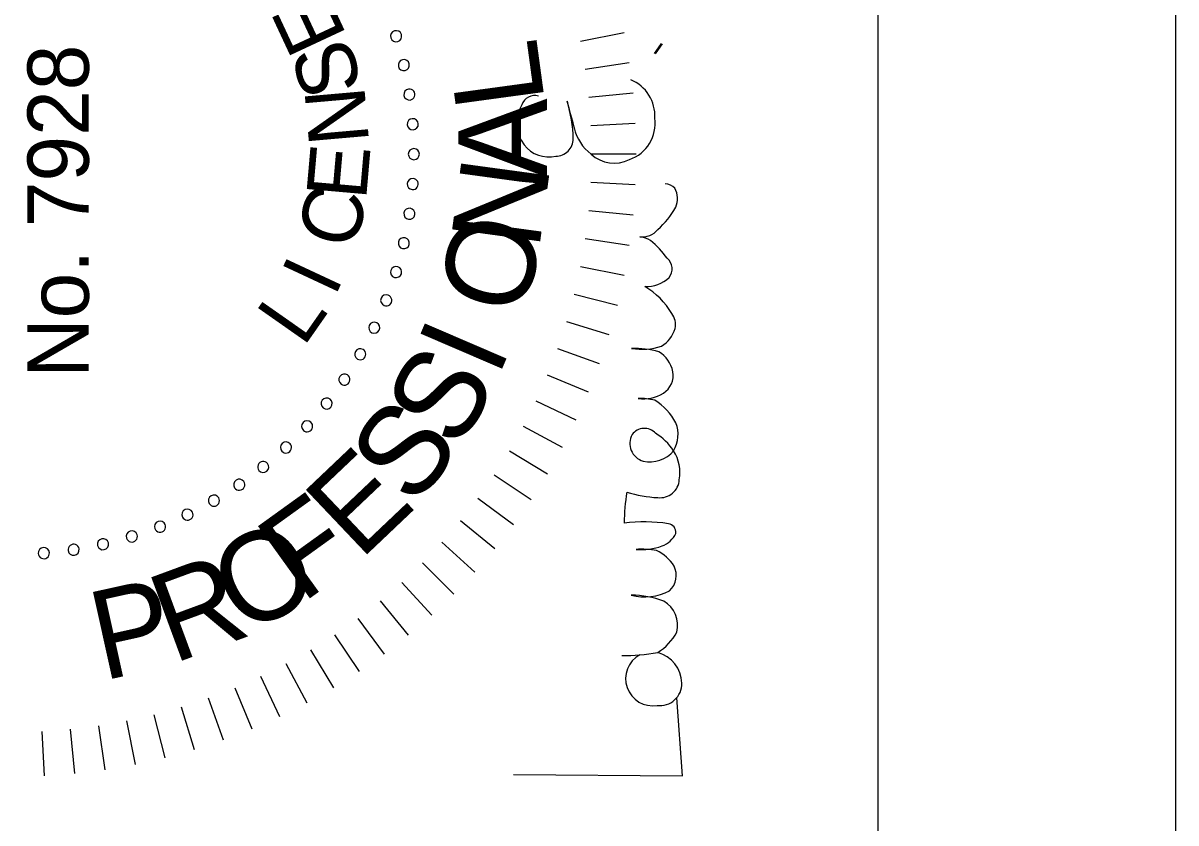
# Model space of a CAD drawing. Extents: x 916887 to 917745, y 329243 to 329793.
# Drawn here: x 917700.26 to 917737.16, y 329615.23 to 329640.82 of the extents above; entities that cross this region are included whole.
import ezdxf

# ---------------------------------------------------------------- set-up
doc = ezdxf.new("R2010")
doc.units = 0
for name, color, linetype in [('Border', 7, 'Continuous'), ('Default', 7, 'Continuous'), ('PLOT BOUNDARY', 7, 'Continuous')]:
    doc.layers.add(name, color=color, linetype=linetype)

# ---------------------------------------------------------------- blocks, each defined once
blk = doc.blocks.new('STAMP')
at = {"layer": 'Default'}
for p, q in [((-0.007955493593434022, 0.0011091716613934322), (-0.007387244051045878, 0.0011370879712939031)), ((-0.007926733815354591, 0.0007192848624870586), (-0.007360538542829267, 0.0007750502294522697)), ((-0.007878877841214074, 0.0003312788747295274), (-0.0073161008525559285, 0.00041475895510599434)), ((-0.007812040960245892, -5.391156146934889e-05), (-0.007254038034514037, 5.708212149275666e-05)), ((-0.0077263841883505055, -0.0004353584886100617), (-0.0071744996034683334, -0.00029711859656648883)), ((-0.007622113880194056, -0.0008121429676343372), (-0.007077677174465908, -0.0006469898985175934)), ((-0.00749948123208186, -0.0011833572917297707), (-0.0069638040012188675, -0.00099168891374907)), ((-0.007358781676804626, -0.0015481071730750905), (-0.006833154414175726, -0.001330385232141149)), ((-0.007200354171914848, -0.0019055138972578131), (-0.006686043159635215, -0.0016622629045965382)), ((-0.007024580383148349, -0.0022547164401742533), (-0.0065228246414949, -0.001986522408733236)), ((-0.006831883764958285, -0.002594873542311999), (-0.006343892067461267, -0.0023023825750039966)), ((-0.006622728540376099, -0.002925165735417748), (-0.0061496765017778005, -0.0026090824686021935)), ((-0.00639761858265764, -0.0032447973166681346), (-0.005940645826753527, -0.0029058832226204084)), ((-0.006157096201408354, -0.003552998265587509), (-0.005717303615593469, -0.0031920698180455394)), ((-0.005901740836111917, -0.003849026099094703), (-0.005480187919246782, -0.0034669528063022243)), ((-0.0056321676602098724, -0.0041321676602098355), (-0.00522986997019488, -0.003729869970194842)), ((-0.005349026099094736, -0.004401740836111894), (-0.004966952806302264, -0.003980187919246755)), ((-0.0050529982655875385, -0.004657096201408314), (-0.004692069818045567, -0.004217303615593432)), ((-0.004744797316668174, -0.0048976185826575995), (-0.004405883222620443, -0.004440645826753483)), ((-0.0044251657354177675, -0.005122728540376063), (-0.004109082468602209, -0.004649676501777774)), ((-0.004094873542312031, -0.005331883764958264), (-0.0038023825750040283, -0.004843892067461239)), ((-0.0037547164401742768, -0.005524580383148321), (-0.0034865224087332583, -0.005022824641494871)), ((-0.003405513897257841, -0.005700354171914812), (-0.0031622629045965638, -0.0051860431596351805)), ((-0.003048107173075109, -0.005858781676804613), (-0.0028303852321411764, -0.005333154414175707)), ((-0.0026833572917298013, -0.005999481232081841), (-0.002491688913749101, -0.005463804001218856)), ((-0.0023121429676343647, -0.006122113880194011), (-0.0021469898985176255, -0.005577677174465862)), ((-0.0019353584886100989, -0.006226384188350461), (-0.0017971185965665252, -0.005674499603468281)), ((-0.0015539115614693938, -0.006312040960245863), (-0.0014429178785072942, -0.005754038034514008)), ((0.0015539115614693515, -0.006312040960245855), (0.0014429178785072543, -0.005754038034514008)), ((-0.001168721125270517, -0.006378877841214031), (-0.0010852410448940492, -0.005816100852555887)), ((-0.0007807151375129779, -0.006426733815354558), (-0.0007249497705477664, -0.0058605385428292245)), ((-0.00039082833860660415, -0.006455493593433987), (-0.00036291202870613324, -0.005887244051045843)), ((-2.0539125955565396e-17, -0.006465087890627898), (-2.0539125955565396e-17, -0.005896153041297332)), ((0.0003908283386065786, -0.0064554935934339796), (0.0003629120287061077, -0.005887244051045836)), ((0.0007807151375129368, -0.006426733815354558), (0.0007249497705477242, -0.005860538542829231)), ((0.0011687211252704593, -0.006378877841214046), (0.0010852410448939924, -0.005816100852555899)), ((0.001282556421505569, -0.006716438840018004), (0.001411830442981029, -0.006805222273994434)), ((0.0012888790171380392, -0.0067038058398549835), (0.0014181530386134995, -0.006792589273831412))]:
    blk.add_line(p, q, dxfattribs=at)
blk.add_lwpolyline([(-0.007938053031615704, -0.004895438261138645), (-0.007956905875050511, -0.007061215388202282), (-0.0069577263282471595, -0.006985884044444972)], dxfattribs=at)
for centre, radius, start, end in [((-0.005106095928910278, 0.0011173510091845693), 7.111685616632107e-05, 94.28571428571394, 274.28571428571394), ((-0.005106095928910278, 0.0011173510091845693), 7.11168561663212e-05, 274.28571428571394, 94.28571428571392), ((-0.005063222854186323, 0.0007368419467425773), 7.111685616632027e-05, 98.5714285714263, 278.5714285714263), ((-0.005063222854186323, 0.0007368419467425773), 7.111685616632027e-05, 278.5714285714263, 98.5714285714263), ((-0.0049920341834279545, 0.00036060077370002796), 7.11168561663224e-05, 102.8571428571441, 282.8571428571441), ((-0.0049920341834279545, 0.00036060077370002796), 7.11168561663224e-05, 282.8571428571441, 102.85714285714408), ((-0.004892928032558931, -9.26841668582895e-06), 7.111685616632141e-05, 107.14285714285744, 287.14285714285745), ((-0.004892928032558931, -9.26841668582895e-06), 7.111685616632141e-05, 287.14285714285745, 107.14285714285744), ((-0.004766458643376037, -0.00037069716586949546), 7.111685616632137e-05, 111.42857142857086, 291.4285714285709), ((-0.004766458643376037, -0.00037069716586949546), 7.111685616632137e-05, 291.4285714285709, 111.42857142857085), ((-0.0046133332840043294, -0.0007216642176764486), 7.1116856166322e-05, 115.71428571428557, 295.71428571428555), ((-0.0046133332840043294, -0.0007216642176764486), 7.1116856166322e-05, 295.71428571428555, 115.71428571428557), ((-0.004434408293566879, -0.0010602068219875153), 7.111685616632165e-05, 119.99999999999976, 299.9999999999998), ((-0.004434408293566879, -0.0010602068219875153), 7.111685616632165e-05, 299.9999999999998, 119.99999999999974), ((-0.004230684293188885, -0.0013844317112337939), 7.111685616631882e-05, 124.28571428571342, 304.2857142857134), ((-0.004230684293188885, -0.0013844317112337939), 7.111685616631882e-05, 304.2857142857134, 124.28571428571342), ((-0.004003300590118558, -0.0016925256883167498), 7.111685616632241e-05, 308.5714285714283, 128.57142857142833), ((-0.004003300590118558, -0.0016925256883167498), 7.111685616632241e-05, 128.57142857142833, 308.5714285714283), ((-0.003753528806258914, -0.0019827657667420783), 7.11168561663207e-05, 312.85714285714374, 132.85714285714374), ((-0.003753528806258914, -0.0019827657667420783), 7.11168561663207e-05, 132.85714285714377, 312.8571428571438), ((-0.0034827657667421, -0.002253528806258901), 7.111685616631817e-05, 137.14285714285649, 317.1428571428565), ((-0.0034827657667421, -0.002253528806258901), 7.111685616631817e-05, 317.1428571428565, 137.14285714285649), ((-0.0031925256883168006, -0.0025033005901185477), 7.111685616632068e-05, 141.42857142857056, 321.42857142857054), ((-0.0031925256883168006, -0.0025033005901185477), 7.111685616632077e-05, 321.42857142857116, 141.4285714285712), ((-0.0028844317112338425, -0.0027306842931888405), 7.111685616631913e-05, 145.7142857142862, 325.71428571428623), ((-0.0028844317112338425, -0.0027306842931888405), 7.111685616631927e-05, 325.7142857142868, 145.71428571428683), ((-0.0025602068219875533, -0.0029344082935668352), 7.111685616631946e-05, 149.99999999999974, 329.9999999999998), ((-0.0025602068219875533, -0.0029344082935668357), 7.111685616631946e-05, 329.9999999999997, 149.99999999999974), ((-0.0022216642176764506, -0.0031133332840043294), 7.111685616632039e-05, 154.2857142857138, 334.28571428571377), ((-0.0022216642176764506, -0.0031133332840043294), 7.111685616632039e-05, 334.2857142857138, 154.2857142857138), ((-0.0018706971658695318, -0.003266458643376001), 7.111685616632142e-05, 158.57142857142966, 338.5714285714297), ((-0.0018706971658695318, -0.0032664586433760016), 7.111685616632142e-05, 338.57142857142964, 158.57142857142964), ((-0.0015092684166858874, -0.003392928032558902), 7.111685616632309e-05, 162.85714285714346, 342.85714285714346), ((-0.0015092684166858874, -0.003392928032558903), 7.111685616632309e-05, 342.85714285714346, 162.85714285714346), ((0.0015092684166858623, -0.0033929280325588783), 7.111685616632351e-05, 17.142857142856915, 197.1428571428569), ((0.0015092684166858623, -0.0033929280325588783), 7.111685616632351e-05, 197.1428571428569, 17.14285714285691), ((-0.0011393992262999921, -0.0034920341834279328), 7.111685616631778e-05, 167.14285714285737, 347.14285714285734), ((-0.0011393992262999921, -0.0034920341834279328), 7.111685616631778e-05, 347.14285714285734, 167.14285714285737), ((-0.0007631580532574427, -0.003563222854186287), 7.111685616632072e-05, 351.4285714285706, 171.4285714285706), ((-0.0003826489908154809, -0.003606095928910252), 7.111685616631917e-05, 355.7142857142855, 175.7142857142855), ((0.0003826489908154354, -0.0036060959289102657), 7.111685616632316e-05, 4.285714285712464, 184.28571428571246), ((0.0007631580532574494, -0.0035632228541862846), 7.111685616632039e-05, 8.571428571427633, 188.57142857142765), ((0.0011393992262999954, -0.0034920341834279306), 7.111685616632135e-05, 12.857142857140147, 192.85714285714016), ((0.0011393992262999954, -0.0034920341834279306), 7.111685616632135e-05, 192.85714285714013, 12.857142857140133), ((-0.0007631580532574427, -0.003563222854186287), 7.111685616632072e-05, 171.4285714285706, 351.4285714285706), ((-0.0003826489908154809, -0.003606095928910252), 7.111685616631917e-05, 175.71428571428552, 355.71428571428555), ((-1.2628786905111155e-17, -0.0036204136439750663), 7.111685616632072e-05, 0, 180), ((-1.2628786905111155e-17, -0.0036204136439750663), 7.111685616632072e-05, 180, 0), ((0.0003826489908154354, -0.0036060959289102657), 7.111685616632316e-05, 184.28571428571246, 4.285714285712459), ((0.0007631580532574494, -0.0035632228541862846), 7.111685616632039e-05, 188.57142857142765, 8.571428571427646), ((0.00039604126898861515, -0.005375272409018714), 0.00043958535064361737, 57.64755033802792, 128.97245422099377), ((0.0005805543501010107, -0.005165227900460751), 0.00016909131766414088, 342.3611945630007, 72.54487353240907), ((0.00036114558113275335, -0.0053488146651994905), 0.0003972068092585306, 127.45926190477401, 192.9614203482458), ((0.00019608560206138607, -0.005439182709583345), 0.0002220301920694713, 179.67057284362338, 269.694601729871), ((0.00015503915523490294, -0.003868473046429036), 0.001793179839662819, 271.2738092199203, 287.01217780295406), ((0.002166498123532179, -0.011827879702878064), 0.006419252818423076, 103.3923944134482, 106.55297850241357), ((0.0004564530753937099, -0.0062299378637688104), 0.0005678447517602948, 102.0773813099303, 143.39383108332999), ((0.00031613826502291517, -0.006186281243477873), 0.0004319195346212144, 136.9297266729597, 206.7934360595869), ((-0.00671307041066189, -0.006678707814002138), 0.0003465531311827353, 28.430349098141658, 189.68707560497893), ((-0.003955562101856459, -0.006312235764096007), 0.002461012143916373, 179.30402472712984, 190.0665804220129), ((-0.007015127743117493, -0.0065631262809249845), 0.0023079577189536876, 352.1195763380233, 6.249520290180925), ((-0.004786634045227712, -0.009314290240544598), 0.003003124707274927, 81.15725195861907, 88.74550427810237), ((-0.002857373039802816, -0.006810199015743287), 0.001539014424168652, 162.47862001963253, 177.5735090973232), ((-0.007040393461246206, -0.006369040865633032), 0.0013973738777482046, 341.03759348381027, 358.5906169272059), ((-0.004987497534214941, -0.006577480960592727), 0.0006786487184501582, 165.1377733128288, 207.96825790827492), ((-0.006329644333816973, -0.006519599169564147), 0.0012732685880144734, 350.5388137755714, 2.446920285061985), ((-0.004310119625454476, -0.006538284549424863), 0.0007509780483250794, 174.41813129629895, 200.30191948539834), ((-0.0037000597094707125, -0.006623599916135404), 0.00023723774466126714, 61.91684207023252, 163.66717131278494), ((-0.0037052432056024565, -0.0065716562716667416), 0.0001960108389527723, 312.7382758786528, 53.40100716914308), ((-0.003974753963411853, -0.006503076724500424), 0.0008496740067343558, 346.26214121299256, 0.7257075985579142), ((-0.002682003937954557, -0.006568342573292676), 0.00044961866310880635, 170.2648919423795, 213.2954708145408), ((-0.00388024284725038, -0.006412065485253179), 0.0013948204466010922, 345.72048696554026, 0.12433676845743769), ((-0.0016914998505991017, -0.006545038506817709), 0.0008054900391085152, 170.27954956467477, 197.78532003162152), ((0.0003962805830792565, -0.006217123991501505), 0.0004936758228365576, 199.38474076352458, 277.55079490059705), ((0.0004891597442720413, -0.006207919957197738), 0.0004993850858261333, 266.784921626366, 337.7362429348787), ((-0.0035430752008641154, -0.006644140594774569), 0.0003944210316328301, 167.2189950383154, 230.16055614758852), ((-0.002536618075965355, -0.006083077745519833), 0.0009765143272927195, 300.6803608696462, 329.51258202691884), ((-0.0012666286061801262, -0.006594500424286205), 0.00042878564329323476, 177.86300386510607, 223.17874837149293), ((-0.0013865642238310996, -0.006474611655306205), 0.0003320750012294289, 327.8843366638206, 353.1980671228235), ((-0.0008025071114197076, -0.006544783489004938), 0.0002561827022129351, 173.08541670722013, 230.55848375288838), ((-0.006777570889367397, -0.006772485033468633), 0.00027937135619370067, 172.70712454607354, 271.16395527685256), ((-0.006783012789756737, -0.006633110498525), 0.0004188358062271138, 271.5209447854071, 344.87406906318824), ((-0.005754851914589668, -0.006345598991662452), 0.0007393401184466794, 212.4592088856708, 240.63114206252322), ((-0.0055308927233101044, -0.006522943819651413), 0.0005014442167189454, 301.1133493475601, 335.74975916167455), ((-0.004152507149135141, -0.006775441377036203), 0.00024439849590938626, 172.85451562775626, 266.8151593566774), ((-0.00421927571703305, -0.006314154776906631), 0.0007614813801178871, 303.79189499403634, 328.18256979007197), ((-0.0038004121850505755, -0.006299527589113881), 0.000766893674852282, 298.0105046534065, 328.09350966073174), ((-0.00285343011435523, -0.006566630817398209), 0.0003761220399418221, 280.5798823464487, 329.7517392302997), ((-0.0020051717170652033, -0.0059200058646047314), 0.0011594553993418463, 305.5205731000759, 320.90595982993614), ((-0.0001785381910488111, -0.0060637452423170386), 0.0010391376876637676, 220.79179678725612, 241.16030041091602), ((-0.006036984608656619, -0.006622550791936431), 0.0003760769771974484, 257.6460165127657, 327.7710077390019), ((-0.005391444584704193, -0.006712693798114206), 0.0002677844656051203, 223.12676578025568, 296.5429712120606), ((-0.004715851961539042, -0.006689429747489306), 0.00031800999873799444, 200.1253724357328, 244.48124886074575), ((-0.004842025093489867, -0.006862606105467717), 0.00011432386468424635, 264.56536252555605, 351.47104640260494), ((-0.0028340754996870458, -0.006679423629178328), 0.00026169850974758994, 211.24435430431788, 280.94854976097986), ((-0.0021179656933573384, -0.00658432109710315), 0.00039838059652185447, 211.26450698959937, 253.32703764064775), ((-0.0021804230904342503, -0.006741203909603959), 0.00023065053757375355, 257.01114107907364, 308.02112433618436), ((-0.0014677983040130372, -0.006749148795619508), 0.0001780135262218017, 231.21384232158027, 319.94914487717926), ((-0.0005623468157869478, -0.006834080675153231), 0.00018159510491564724, 314.66347430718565, 358.2957841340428), ((-0.00407546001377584, -0.006500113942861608), 0.0005271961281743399, 260.1016649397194, 302.042575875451), ((-0.0035868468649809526, -0.00658750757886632), 0.00041578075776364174, 239.8376850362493, 290.64484911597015), ((-0.0005688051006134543, -0.006705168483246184), 0.00029083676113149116, 247.5695171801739, 297.4590386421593)]:
    blk.add_arc(centre, radius, start, end, dxfattribs=at)
for s, height, p in [('No. 7928', 0.0007851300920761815, (-0.002860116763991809, 0.0005420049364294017)), ('A', 0.0011378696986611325, (-0.0003007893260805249, -0.005327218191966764))]:
    blk.add_text(s, height=height, dxfattribs=at).set_placement(p)
for s, height, rotation, p in [('P', 0.0011378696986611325, 282.5, (-0.006741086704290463, 0.00036378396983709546)), ('R', 0.0011378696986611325, 290.25, (-0.00652629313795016, -0.0005348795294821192)), ('O', 0.0011378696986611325, 298, (-0.006169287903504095, -0.0014396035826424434)), ('F', 0.001137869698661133, 305.75, (-0.0057573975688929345, -0.002187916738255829)), ('L', 0.0007680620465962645, 324.99999999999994, (-0.002479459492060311, -0.00220631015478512)), ('E', 0.0007680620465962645, 25.000000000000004, (0.001513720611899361, -0.002766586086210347)), ('I', 0.0007680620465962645, 335, (-0.001841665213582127, -0.002604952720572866)), ('C', 0.0007680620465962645, 345, (-0.0012469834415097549, -0.0028524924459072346)), ('S', 0.0007680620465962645, 14.999999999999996, (0.0008506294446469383, -0.0029637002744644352)), ('E', 0.0011378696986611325, 313.5, (-0.005207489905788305, -0.0029306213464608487)), ('E', 0.0007680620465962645, 355, (-0.0005969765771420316, -0.00300722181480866)), ('N', 0.0007680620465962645, 5, (0.0001499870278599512, -0.003047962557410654)), ('S', 0.0011378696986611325, 321.25, (-0.004535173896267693, -0.0036142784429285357)), ('S', 0.0011378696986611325, 328.99999999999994, (-0.003804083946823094, -0.004179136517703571)), ('I', 0.0011378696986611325, 336.75, (-0.0028749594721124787, -0.00469547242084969)), ('O', 0.001137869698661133, 344.5, (-0.0021143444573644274, -0.004998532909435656)), ('N', 0.001137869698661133, 352.25, (-0.001239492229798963, -0.005221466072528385)), ('L', 0.001137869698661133, 7.75, (0.0006711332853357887, -0.0052988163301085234))]:
    blk.add_text(s, height=height, rotation=rotation, dxfattribs=at).set_placement(p)

msp = doc.modelspace()

# ---------------------------------------------------------------- linework, layer by layer
at = {"layer": 'Border'}
msp.add_line((917727.630894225, 329258.0107371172), (917727.630894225, 329783.00968711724), dxfattribs=at)
at = {"layer": 'PLOT BOUNDARY'}
msp.add_lwpolyline([(916887.1658435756, 329242.7002039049), (917737.1641435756, 329242.7002039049), (917737.1641435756, 329792.6991039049), (916887.1658435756, 329792.6991039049)], close=True, dxfattribs=at)

# ---------------------------------------------------------------- block references
at = {"layer": 'Border', "xscale": 2499.999999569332, "yscale": 2499.999999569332, "rotation": 90}
msp.add_blockref('STAMP', (917703.7166483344, 329636.6288155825), dxfattribs=at)

doc.saveas('drawing.dxf')
